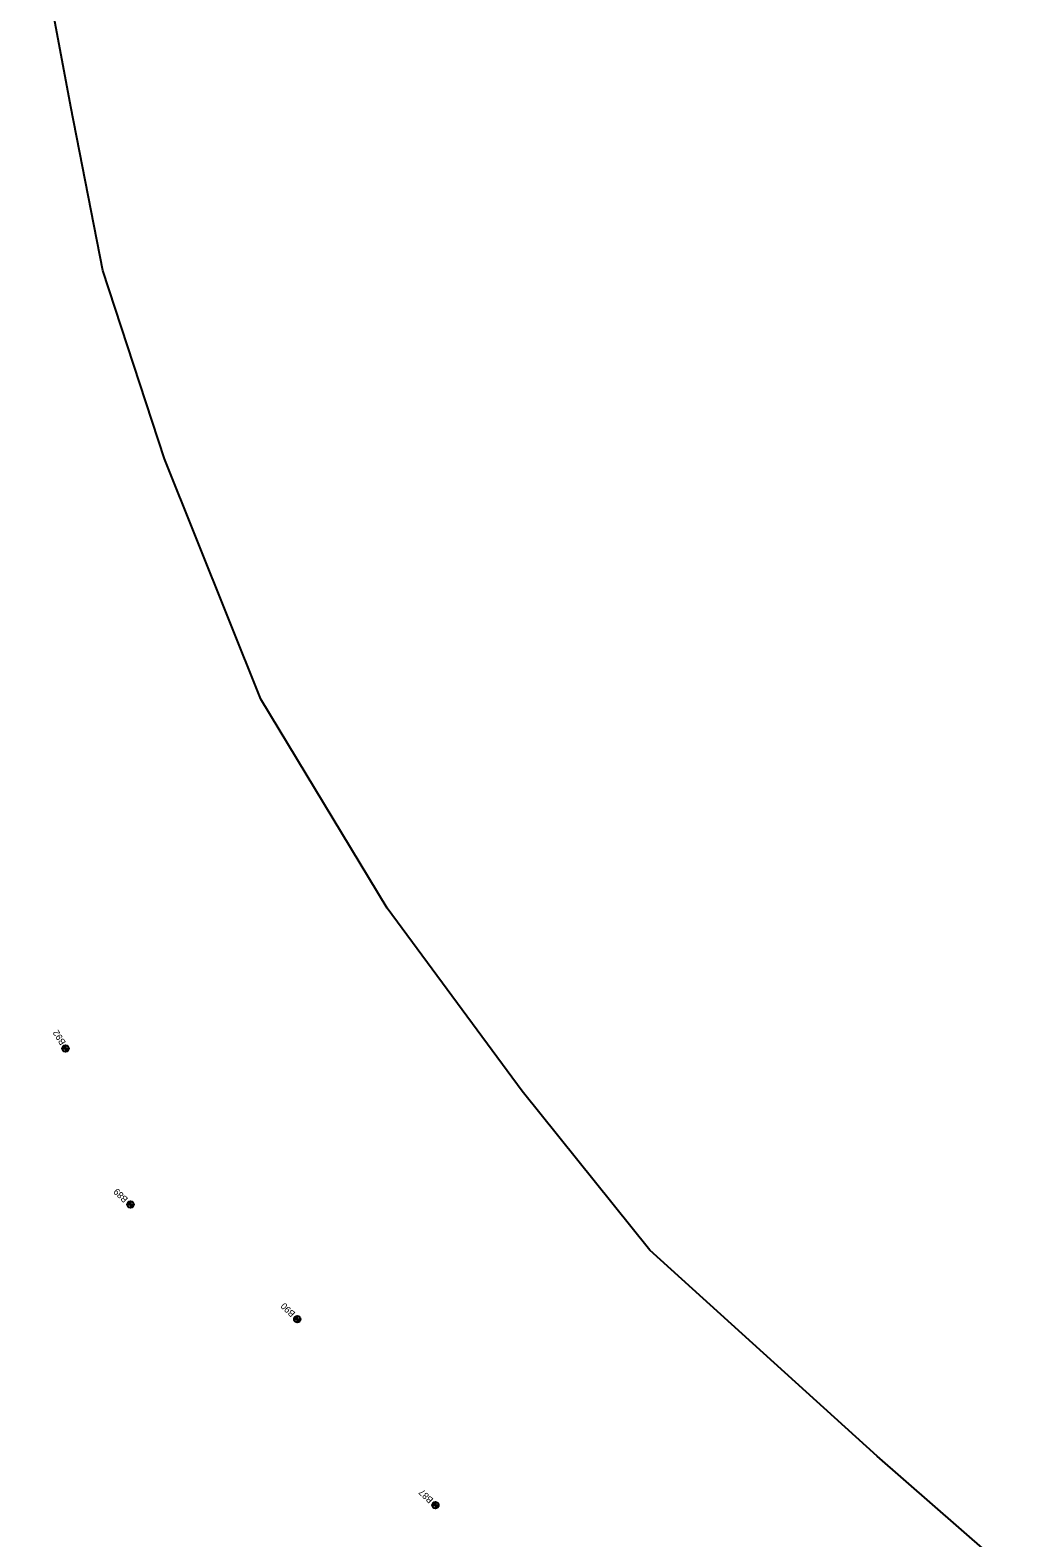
# Model space of a CAD drawing. Extents: x 311409 to 379449, y 121539 to 224848.
# Drawn here: x 356761 to 358282, y 178592 to 180901 of the extents above; entities that cross this region are included whole.
import ezdxf

# ---------------------------------------------------------------- set-up
doc = ezdxf.new("R2010")
doc.units = 0
for name, color, linetype in [('E_SOIL_BORE1 [KAPUR_CADDS_LEVELS]', 7, 'Continuous'), ('E_SOIL_BORE2 [KAPUR_CADDS_LEVELS]', 7, 'Continuous'), ('P_MARK', 7, 'Continuous'), ('P_TC', 7, 'Continuous')]:
    doc.layers.add(name, color=color, linetype=linetype)

msp = doc.modelspace()

# ---------------------------------------------------------------- linework, layer by layer
at = {"layer": 'P_MARK'}
for p, q in [((356810.5, 179341.5), (356820.5, 179341.5)), ((356815.5, 179346.5), (356815.5, 179336.5)), ((356910, 179102.8), (356920, 179102.8)), ((356915, 179107.8), (356915, 179097.8)), ((357165.2, 178927.2), (357175.2, 178927.2)), ((357170.2, 178932.2), (357170.2, 178922.2)), ((357376.6, 178642.3), (357386.6, 178642.3)), ((357381.6, 178647.3), (357381.6, 178637.3))]:
    msp.add_line(p, q, dxfattribs=at)
for centre in [(356815.5, 179341.5), (356915, 179102.8), (357170.2, 178927.2), (357381.6, 178642.3)]:
    msp.add_circle(centre, 5, dxfattribs=at)
for centre, radius, start, end in [((356815.5, 179341.5), 4.5, 89.9869, 179.9869), ((356815.5, 179341.5), 4, 89.9869, 179.9869), ((356815.5, 179341.5), 3.5, 89.9869, 179.9869), ((356815.5, 179341.5), 3, 89.9869, 179.9869), ((356815.5, 179341.5), 2.5, 89.9869, 179.9869), ((356815.5, 179341.5), 2, 89.9869, 179.9869), ((356815.5, 179341.5), 1.5, 89.9869, 179.9869), ((356815.5, 179341.5), 1, 89.9869, 179.9869), ((356815.5, 179341.5), 0.5, 89.9869, 179.9869), ((356815.5, 179341.5), 4.5, 269.9869, 359.9869), ((356815.5, 179341.5), 4, 269.9869, 359.9869), ((356815.5, 179341.5), 3.5, 269.9869, 359.9869), ((356815.5, 179341.5), 3, 269.9869, 359.9869), ((356815.5, 179341.5), 2.5, 269.9869, 359.9869), ((356815.5, 179341.5), 2, 269.9869, 359.9869), ((356815.5, 179341.5), 1.5, 269.9869, 359.9869), ((356815.5, 179341.5), 1, 269.9869, 359.9869), ((356815.5, 179341.5), 0.5, 269.9869, 359.9869), ((356915, 179102.8), 4.5, 89.9869, 179.9869), ((356915, 179102.8), 4, 89.9869, 179.9869), ((356915, 179102.8), 3.5, 89.9869, 179.9869), ((356915, 179102.8), 3, 89.9869, 179.9869), ((356915, 179102.8), 2.5, 89.9869, 179.9869), ((356915, 179102.8), 2, 89.9869, 179.9869), ((356915, 179102.8), 1.5, 89.9869, 179.9869), ((356915, 179102.8), 1, 89.9869, 179.9869), ((356915, 179102.8), 0.5, 89.9869, 179.9869), ((356915, 179102.8), 4.5, 269.9869, 359.9869), ((356915, 179102.8), 4, 269.9869, 359.9869), ((356915, 179102.8), 3.5, 269.9869, 359.9869), ((356915, 179102.8), 3, 269.9869, 359.9869), ((356915, 179102.8), 2.5, 269.9869, 359.9869), ((356915, 179102.8), 2, 269.9869, 359.9869), ((356915, 179102.8), 1.5, 269.9869, 359.9869), ((356915, 179102.8), 1, 269.9869, 359.9869), ((356915, 179102.8), 0.5, 269.9869, 359.9869), ((357170.2, 178927.2), 4.5, 89.9869, 179.9869), ((357170.2, 178927.2), 4, 89.9869, 179.9869), ((357170.2, 178927.2), 3.5, 89.9869, 179.9869), ((357170.2, 178927.2), 3, 89.9869, 179.9869), ((357170.2, 178927.2), 2.5, 89.9869, 179.9869), ((357170.2, 178927.2), 2, 89.9869, 179.9869), ((357170.2, 178927.2), 1.5, 89.9869, 179.9869), ((357170.2, 178927.2), 1, 89.9869, 179.9869), ((357170.2, 178927.2), 0.5, 89.9869, 179.9869), ((357170.2, 178927.2), 4.5, 269.9869, 359.9869), ((357170.2, 178927.2), 4, 269.9869, 359.9869), ((357170.2, 178927.2), 3.5, 269.9869, 359.9869), ((357170.2, 178927.2), 3, 269.9869, 359.9869), ((357170.2, 178927.2), 2.5, 269.9869, 359.9869), ((357170.2, 178927.2), 2, 269.9869, 359.9869), ((357170.2, 178927.2), 1.5, 269.9869, 359.9869), ((357170.2, 178927.2), 1, 269.9869, 359.9869), ((357170.2, 178927.2), 0.5, 269.9869, 359.9869), ((357381.6, 178642.3), 4.5, 89.9869, 179.9869), ((357381.6, 178642.3), 4, 89.9869, 179.9869), ((357381.6, 178642.3), 3.5, 89.9869, 179.9869), ((357381.6, 178642.3), 3, 89.9869, 179.9869), ((357381.6, 178642.3), 2.5, 89.9869, 179.9869), ((357381.6, 178642.3), 2, 89.9869, 179.9869), ((357381.6, 178642.3), 1.5, 89.9869, 179.9869), ((357381.6, 178642.3), 1, 89.9869, 179.9869), ((357381.6, 178642.3), 0.5, 89.9869, 179.9869), ((357381.6, 178642.3), 4.5, 269.9869, 359.9869), ((357381.6, 178642.3), 4, 269.9869, 359.9869), ((357381.6, 178642.3), 3.5, 269.9869, 359.9869), ((357381.6, 178642.3), 3, 269.9869, 359.9869), ((357381.6, 178642.3), 2.5, 269.9869, 359.9869), ((357381.6, 178642.3), 2, 269.9869, 359.9869), ((357381.6, 178642.3), 1.5, 269.9869, 359.9869), ((357381.6, 178642.3), 1, 269.9869, 359.9869), ((357381.6, 178642.3), 0.5, 269.9869, 359.9869)]:
    msp.add_arc(centre, radius, start, end, dxfattribs=at)
at = {"layer": 'P_TC'}
msp.add_lwpolyline([(360564.9, 171534.5), (360796.6, 174469.4), (360628.3, 175702.2), (360517.9, 176032.1), (360348.2, 176426), (360166.8, 176728.9), (359962.3, 177020), (359692, 177345), (359392.9, 177648.7), (359162.3, 177826.9), (359016.4, 177939.7), (358396.6, 178421.6), (358058.1, 178717.6), (357710, 179032.7), (357514.4, 179276.3), (357307.6, 179556.6), (357114.4, 179876.4), (356967.1, 180244.4), (356872.7, 180532.7), (356823.5, 180783.3), (356761.3, 181116.1)], dxfattribs=at)

# ---------------------------------------------------------------- texts
at = {"layer": 'E_SOIL_BORE1 [KAPUR_CADDS_LEVELS]'}
for s, p in [('B89', (356911.8, 179111.8)), ('B90', (357167.8, 178936.6)), ('B87', (357379.1, 178651.4))]:
    msp.add_text(s, height=10, rotation=136.1942, dxfattribs=at).set_placement(p)
at = {"layer": 'E_SOIL_BORE2 [KAPUR_CADDS_LEVELS]'}
msp.add_text('B92', height=10, rotation=121.7799, dxfattribs=at).set_placement((356816.3, 179350.8))

doc.saveas('drawing.dxf')
